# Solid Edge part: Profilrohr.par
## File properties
Username: bmolnar
Dokumentum tartalom típus: 0
Author: bmolnar
Last saved by: bmolnar
Revision: 82
Sűrűség: 0,000 kg/m^3
Pontosság: 0,990
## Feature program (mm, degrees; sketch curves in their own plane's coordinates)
base feature "unnamed BaseFeature 1"
thread "unnamed Thread 1"
thread "Menet_2"  ThreadDepth = 5.5 mm
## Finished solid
Body 1: solid body, 127 faces, 307 edges, 198 vertices.
  Faces by surface: cylinder 57, plane 52, cone 16, torus 2
  Edges by curve: line 144, circle 142, spline 9, curve on surface 7, intersection 5
Bounding box of the edges (mm; curved faces can reach further): 30.000 x 34.000 x 63.000, from (-15, -15, 0) to (15, 19, 63).
Cylindrical faces by radius (mm): R0.3 x24, R0.65 x2, R1.85 x4, R2 x2, R2.067 x4, R2.35 x2, R2.8 x4, R3.75 x4, R8 x1, R8.95 x2, R9.1 x2, R9.5 x2, R20 x4
Conical faces (half-angle, radius in mm at the cone's reference point): 45 deg R2.317 x2, 45 deg R2.95 x4, 45 deg R3.9 x4, 45 deg R8.4 x2, 45 deg R9.2 x2, 45 deg R9.25 x2
Toroidal faces (ring radius, tube radius in mm): R9.4 r0.1 x2
Planar faces by outward normal: +x 6, +y 9, +z 9, -x 6, -y 5, -z 9, oblique 8
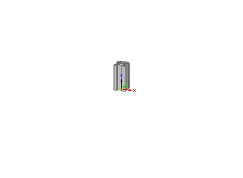
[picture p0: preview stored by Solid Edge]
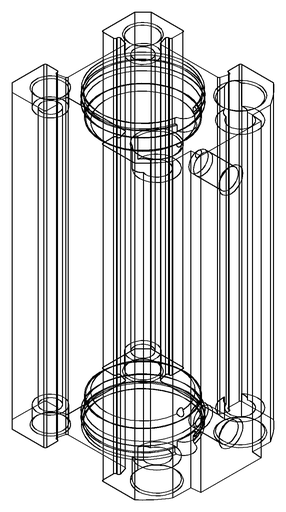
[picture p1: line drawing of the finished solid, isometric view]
